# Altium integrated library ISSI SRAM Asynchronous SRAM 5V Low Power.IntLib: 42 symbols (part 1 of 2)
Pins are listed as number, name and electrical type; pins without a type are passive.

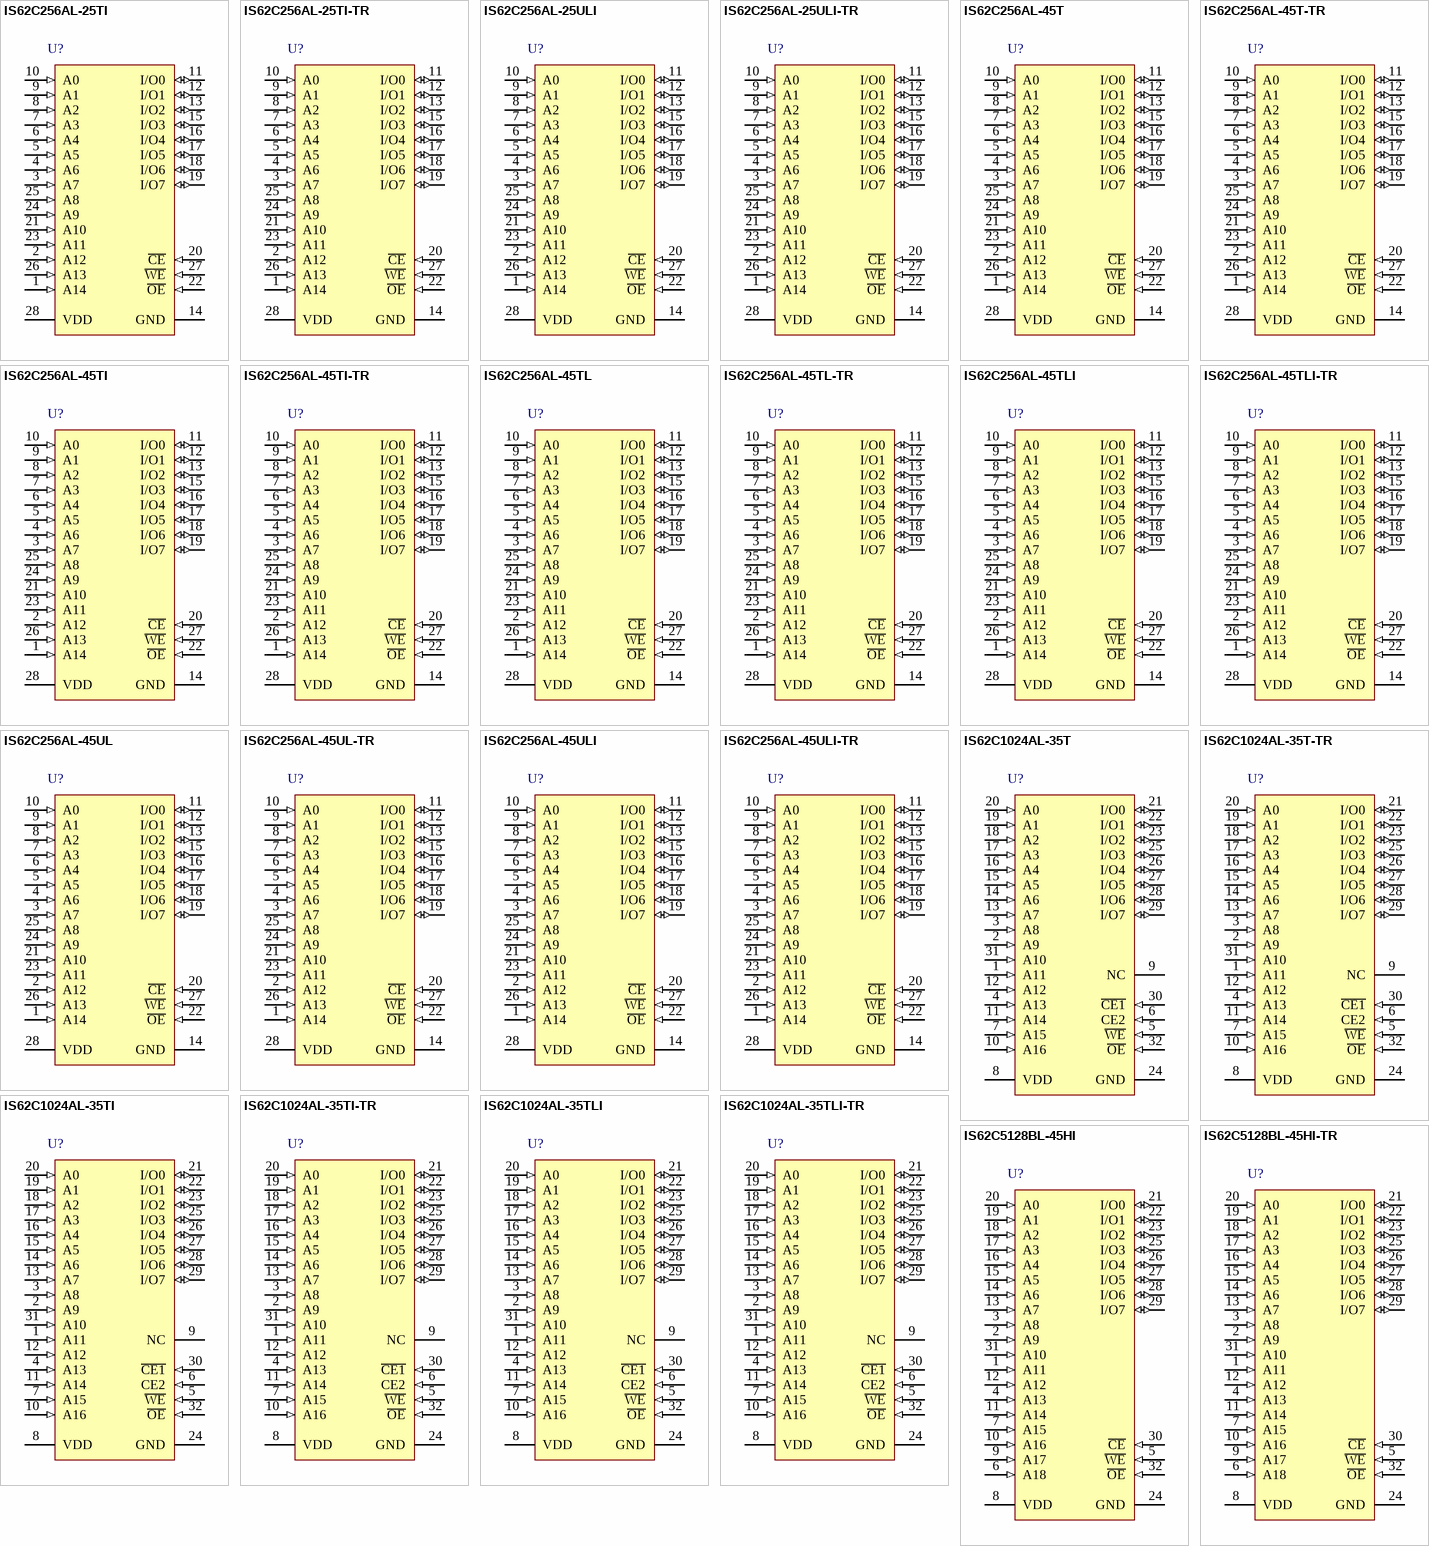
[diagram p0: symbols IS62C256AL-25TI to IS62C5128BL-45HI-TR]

## IS62C256AL-25TI
designator U?
256 K Low Power CMOS SRAM, 32 K x 8, -40 to 85 degC, 28-Pin SOP (TSOP-1-28); Manufacturer: Integrated Silicon Solution Inc (ISSI); PartNumber: IS62C256AL-25TI; Density: 256K; Organization: 32K x 8; Packing: Tray / Tube; Speed (ns): 25
footprint ISSI-TSOP-1-28-8000X13400DE_N (SOP, 28-Leads, Body 11.9x8.1mm, Pitch 0.55mm, IPC Medium Density)
pins: 1 A14 (in) "Address Input", 2 A12 (in) "Address Input", 3 A7 (in) "Address Input", 4 A6 (in) "Address Input", 5 A5 (in) "Address Input", 6 A4 (in) "Address Input", 7 A3 (in) "Address Input", 8 A2 (in) "Address Input", 9 A1 (in) "Address Input", 10 A0 (in) "Address Input", 11 I/O0 (io) "Input/Output", 12 I/O1 (io) "Input/Output", 13 I/O2 (io) "Input/Output", 14 GND (power) "Ground", 15 I/O3 (io) "Input/Output", 16 I/O4 (io) "Input/Output", 17 I/O5 (io) "Input/Output", 18 I/O6 (io) "Input/Output", 19 I/O7 (io) "Input/Output", 20 ~{CE} (in) "Chip Select Input", 21 A10 (in) "Address Input", 22 ~{OE} (in) "Output Enable Input", 23 A11 (in) "Address Input", 24 A9 (in) "Address Input", 25 A8 (in) "Address Input", 26 A13 (in) "Address Input", 27 ~{WE} (in) "Write Enable Input", 28 VDD (power) "Power"

## IS62C256AL-25TI-TR
designator U?
256 K Low Power CMOS SRAM, 32 K x 8, -40 to 85 degC, 28-Pin SOP (TSOP-1-28); Manufacturer: Integrated Silicon Solution Inc (ISSI); PartNumber: IS62C256AL-25TI-TR; Density: 256K; Organization: 32K x 8; Packing: Tape & Reel; Speed (ns): 25
footprint ISSI-TSOP-1-28-8000X13400DE_N (SOP, 28-Leads, Body 11.9x8.1mm, Pitch 0.55mm, IPC Medium Density)
pins: 1 A14 (in) "Address Input", 2 A12 (in) "Address Input", 3 A7 (in) "Address Input", 4 A6 (in) "Address Input", 5 A5 (in) "Address Input", 6 A4 (in) "Address Input", 7 A3 (in) "Address Input", 8 A2 (in) "Address Input", 9 A1 (in) "Address Input", 10 A0 (in) "Address Input", 11 I/O0 (io) "Input/Output", 12 I/O1 (io) "Input/Output", 13 I/O2 (io) "Input/Output", 14 GND (power) "Ground", 15 I/O3 (io) "Input/Output", 16 I/O4 (io) "Input/Output", 17 I/O5 (io) "Input/Output", 18 I/O6 (io) "Input/Output", 19 I/O7 (io) "Input/Output", 20 ~{CE} (in) "Chip Select Input", 21 A10 (in) "Address Input", 22 ~{OE} (in) "Output Enable Input", 23 A11 (in) "Address Input", 24 A9 (in) "Address Input", 25 A8 (in) "Address Input", 26 A13 (in) "Address Input", 27 ~{WE} (in) "Write Enable Input", 28 VDD (power) "Power"

## IS62C256AL-25ULI
designator U?
256 K Low Power CMOS SRAM, 32 K x 8, -40 to 85 degC, 28-Pin SOP (SOP-28), Pb-Free; Manufacturer: Integrated Silicon Solution Inc (ISSI); PartNumber: IS62C256AL-25ULI; Density: 256K; Organization: 32K x 8; Packing: Tray / Tube; Speed (ns): 25
footprint ISSI-SOP-28_N (SOP, 28-Leads, Body 18.66x8.9mm, Pitch 1.27mm, IPC Medium Density)
pins: 1 A14 (in) "Address Input", 2 A12 (in) "Address Input", 3 A7 (in) "Address Input", 4 A6 (in) "Address Input", 5 A5 (in) "Address Input", 6 A4 (in) "Address Input", 7 A3 (in) "Address Input", 8 A2 (in) "Address Input", 9 A1 (in) "Address Input", 10 A0 (in) "Address Input", 11 I/O0 (io) "Input/Output", 12 I/O1 (io) "Input/Output", 13 I/O2 (io) "Input/Output", 14 GND (power) "Ground", 15 I/O3 (io) "Input/Output", 16 I/O4 (io) "Input/Output", 17 I/O5 (io) "Input/Output", 18 I/O6 (io) "Input/Output", 19 I/O7 (io) "Input/Output", 20 ~{CE} (in) "Chip Select Input", 21 A10 (in) "Address Input", 22 ~{OE} (in) "Output Enable Input", 23 A11 (in) "Address Input", 24 A9 (in) "Address Input", 25 A8 (in) "Address Input", 26 A13 (in) "Address Input", 27 ~{WE} (in) "Write Enable Input", 28 VDD (power) "Power"

## IS62C256AL-25ULI-TR
designator U?
256 K Low Power CMOS SRAM, 32 K x 8, -40 to 85 degC, 28-Pin SOP (SOP-28), Pb-Free; Manufacturer: Integrated Silicon Solution Inc (ISSI); PartNumber: IS62C256AL-25ULI-TR; Density: 256K; Organization: 32K x 8; Packing: Tape & Reel; Speed (ns): 25
footprint ISSI-SOP-28_N (SOP, 28-Leads, Body 18.66x8.9mm, Pitch 1.27mm, IPC Medium Density)
pins: 1 A14 (in) "Address Input", 2 A12 (in) "Address Input", 3 A7 (in) "Address Input", 4 A6 (in) "Address Input", 5 A5 (in) "Address Input", 6 A4 (in) "Address Input", 7 A3 (in) "Address Input", 8 A2 (in) "Address Input", 9 A1 (in) "Address Input", 10 A0 (in) "Address Input", 11 I/O0 (io) "Input/Output", 12 I/O1 (io) "Input/Output", 13 I/O2 (io) "Input/Output", 14 GND (power) "Ground", 15 I/O3 (io) "Input/Output", 16 I/O4 (io) "Input/Output", 17 I/O5 (io) "Input/Output", 18 I/O6 (io) "Input/Output", 19 I/O7 (io) "Input/Output", 20 ~{CE} (in) "Chip Select Input", 21 A10 (in) "Address Input", 22 ~{OE} (in) "Output Enable Input", 23 A11 (in) "Address Input", 24 A9 (in) "Address Input", 25 A8 (in) "Address Input", 26 A13 (in) "Address Input", 27 ~{WE} (in) "Write Enable Input", 28 VDD (power) "Power"

## IS62C256AL-45T
designator U?
256 K Low Power CMOS SRAM, 32 K x 8, 0 to 70 degC, 28-Pin SOP (TSOP-1-28); Manufacturer: Integrated Silicon Solution Inc (ISSI); PartNumber: IS62C256AL-45T; Density: 256K; Organization: 32K x 8; Packing: Tray / Tube; Speed (ns): 45
footprint ISSI-TSOP-1-28-8000X13400DE_N (SOP, 28-Leads, Body 11.9x8.1mm, Pitch 0.55mm, IPC Medium Density)
pins: 1 A14 (in) "Address Input", 2 A12 (in) "Address Input", 3 A7 (in) "Address Input", 4 A6 (in) "Address Input", 5 A5 (in) "Address Input", 6 A4 (in) "Address Input", 7 A3 (in) "Address Input", 8 A2 (in) "Address Input", 9 A1 (in) "Address Input", 10 A0 (in) "Address Input", 11 I/O0 (io) "Input/Output", 12 I/O1 (io) "Input/Output", 13 I/O2 (io) "Input/Output", 14 GND (power) "Ground", 15 I/O3 (io) "Input/Output", 16 I/O4 (io) "Input/Output", 17 I/O5 (io) "Input/Output", 18 I/O6 (io) "Input/Output", 19 I/O7 (io) "Input/Output", 20 ~{CE} (in) "Chip Select Input", 21 A10 (in) "Address Input", 22 ~{OE} (in) "Output Enable Input", 23 A11 (in) "Address Input", 24 A9 (in) "Address Input", 25 A8 (in) "Address Input", 26 A13 (in) "Address Input", 27 ~{WE} (in) "Write Enable Input", 28 VDD (power) "Power"

## IS62C256AL-45T-TR
designator U?
256 K Low Power CMOS SRAM, 32 K x 8, 0 to 70 degC, 28-Pin SOP (TSOP-1-28); Manufacturer: Integrated Silicon Solution Inc (ISSI); PartNumber: IS62C256AL-45T-TR; Density: 256K; Organization: 32K x 8; Packing: Tape & Reel; Speed (ns): 45
footprint ISSI-TSOP-1-28-8000X13400DE_N (SOP, 28-Leads, Body 11.9x8.1mm, Pitch 0.55mm, IPC Medium Density)
pins: 1 A14 (in) "Address Input", 2 A12 (in) "Address Input", 3 A7 (in) "Address Input", 4 A6 (in) "Address Input", 5 A5 (in) "Address Input", 6 A4 (in) "Address Input", 7 A3 (in) "Address Input", 8 A2 (in) "Address Input", 9 A1 (in) "Address Input", 10 A0 (in) "Address Input", 11 I/O0 (io) "Input/Output", 12 I/O1 (io) "Input/Output", 13 I/O2 (io) "Input/Output", 14 GND (power) "Ground", 15 I/O3 (io) "Input/Output", 16 I/O4 (io) "Input/Output", 17 I/O5 (io) "Input/Output", 18 I/O6 (io) "Input/Output", 19 I/O7 (io) "Input/Output", 20 ~{CE} (in) "Chip Select Input", 21 A10 (in) "Address Input", 22 ~{OE} (in) "Output Enable Input", 23 A11 (in) "Address Input", 24 A9 (in) "Address Input", 25 A8 (in) "Address Input", 26 A13 (in) "Address Input", 27 ~{WE} (in) "Write Enable Input", 28 VDD (power) "Power"

## IS62C256AL-45TI
designator U?
256 K Low Power CMOS SRAM, 32 K x 8, -40 to 85 degC, 28-Pin SOP (TSOP-1-28); Manufacturer: Integrated Silicon Solution Inc (ISSI); PartNumber: IS62C256AL-45TI; Density: 256K; Organization: 32K x 8; Packing: Tray / Tube; Speed (ns): 45
footprint ISSI-TSOP-1-28-8000X13400DE_N (SOP, 28-Leads, Body 11.9x8.1mm, Pitch 0.55mm, IPC Medium Density)
pins: 1 A14 (in) "Address Input", 2 A12 (in) "Address Input", 3 A7 (in) "Address Input", 4 A6 (in) "Address Input", 5 A5 (in) "Address Input", 6 A4 (in) "Address Input", 7 A3 (in) "Address Input", 8 A2 (in) "Address Input", 9 A1 (in) "Address Input", 10 A0 (in) "Address Input", 11 I/O0 (io) "Input/Output", 12 I/O1 (io) "Input/Output", 13 I/O2 (io) "Input/Output", 14 GND (power) "Ground", 15 I/O3 (io) "Input/Output", 16 I/O4 (io) "Input/Output", 17 I/O5 (io) "Input/Output", 18 I/O6 (io) "Input/Output", 19 I/O7 (io) "Input/Output", 20 ~{CE} (in) "Chip Select Input", 21 A10 (in) "Address Input", 22 ~{OE} (in) "Output Enable Input", 23 A11 (in) "Address Input", 24 A9 (in) "Address Input", 25 A8 (in) "Address Input", 26 A13 (in) "Address Input", 27 ~{WE} (in) "Write Enable Input", 28 VDD (power) "Power"

## IS62C256AL-45TI-TR
designator U?
256 K Low Power CMOS SRAM, 32 K x 8, -40 to 85 degC, 28-Pin SOP (TSOP-1-28); Manufacturer: Integrated Silicon Solution Inc (ISSI); PartNumber: IS62C256AL-45TI-TR; Density: 256K; Organization: 32K x 8; Packing: Tape & Reel; Speed (ns): 45
footprint ISSI-TSOP-1-28-8000X13400DE_N (SOP, 28-Leads, Body 11.9x8.1mm, Pitch 0.55mm, IPC Medium Density)
pins: 1 A14 (in) "Address Input", 2 A12 (in) "Address Input", 3 A7 (in) "Address Input", 4 A6 (in) "Address Input", 5 A5 (in) "Address Input", 6 A4 (in) "Address Input", 7 A3 (in) "Address Input", 8 A2 (in) "Address Input", 9 A1 (in) "Address Input", 10 A0 (in) "Address Input", 11 I/O0 (io) "Input/Output", 12 I/O1 (io) "Input/Output", 13 I/O2 (io) "Input/Output", 14 GND (power) "Ground", 15 I/O3 (io) "Input/Output", 16 I/O4 (io) "Input/Output", 17 I/O5 (io) "Input/Output", 18 I/O6 (io) "Input/Output", 19 I/O7 (io) "Input/Output", 20 ~{CE} (in) "Chip Select Input", 21 A10 (in) "Address Input", 22 ~{OE} (in) "Output Enable Input", 23 A11 (in) "Address Input", 24 A9 (in) "Address Input", 25 A8 (in) "Address Input", 26 A13 (in) "Address Input", 27 ~{WE} (in) "Write Enable Input", 28 VDD (power) "Power"

## IS62C256AL-45TL
designator U?
256 K Low Power CMOS SRAM, 32 K x 8, 0 to 70 degC, 28-Pin SOP (TSOP-1-28), Pb-Free; Manufacturer: Integrated Silicon Solution Inc (ISSI); PartNumber: IS62C256AL-45TL; Density: 256K; Organization: 32K x 8; Packing: Tray / Tube; Speed (ns): 45
footprint ISSI-TSOP-1-28-8000X13400DE_N (SOP, 28-Leads, Body 11.9x8.1mm, Pitch 0.55mm, IPC Medium Density)
pins: 1 A14 (in) "Address Input", 2 A12 (in) "Address Input", 3 A7 (in) "Address Input", 4 A6 (in) "Address Input", 5 A5 (in) "Address Input", 6 A4 (in) "Address Input", 7 A3 (in) "Address Input", 8 A2 (in) "Address Input", 9 A1 (in) "Address Input", 10 A0 (in) "Address Input", 11 I/O0 (io) "Input/Output", 12 I/O1 (io) "Input/Output", 13 I/O2 (io) "Input/Output", 14 GND (power) "Ground", 15 I/O3 (io) "Input/Output", 16 I/O4 (io) "Input/Output", 17 I/O5 (io) "Input/Output", 18 I/O6 (io) "Input/Output", 19 I/O7 (io) "Input/Output", 20 ~{CE} (in) "Chip Select Input", 21 A10 (in) "Address Input", 22 ~{OE} (in) "Output Enable Input", 23 A11 (in) "Address Input", 24 A9 (in) "Address Input", 25 A8 (in) "Address Input", 26 A13 (in) "Address Input", 27 ~{WE} (in) "Write Enable Input", 28 VDD (power) "Power"

## IS62C256AL-45TL-TR
designator U?
256 K Low Power CMOS SRAM, 32 K x 8, 0 to 70 degC, 28-Pin SOP (TSOP-1-28), Pb-Free; Manufacturer: Integrated Silicon Solution Inc (ISSI); PartNumber: IS62C256AL-45TL-TR; Density: 256K; Organization: 32K x 8; Packing: Tape & Reel; Speed (ns): 45
footprint ISSI-TSOP-1-28-8000X13400DE_N (SOP, 28-Leads, Body 11.9x8.1mm, Pitch 0.55mm, IPC Medium Density)
pins: 1 A14 (in) "Address Input", 2 A12 (in) "Address Input", 3 A7 (in) "Address Input", 4 A6 (in) "Address Input", 5 A5 (in) "Address Input", 6 A4 (in) "Address Input", 7 A3 (in) "Address Input", 8 A2 (in) "Address Input", 9 A1 (in) "Address Input", 10 A0 (in) "Address Input", 11 I/O0 (io) "Input/Output", 12 I/O1 (io) "Input/Output", 13 I/O2 (io) "Input/Output", 14 GND (power) "Ground", 15 I/O3 (io) "Input/Output", 16 I/O4 (io) "Input/Output", 17 I/O5 (io) "Input/Output", 18 I/O6 (io) "Input/Output", 19 I/O7 (io) "Input/Output", 20 ~{CE} (in) "Chip Select Input", 21 A10 (in) "Address Input", 22 ~{OE} (in) "Output Enable Input", 23 A11 (in) "Address Input", 24 A9 (in) "Address Input", 25 A8 (in) "Address Input", 26 A13 (in) "Address Input", 27 ~{WE} (in) "Write Enable Input", 28 VDD (power) "Power"

## IS62C256AL-45TLI
designator U?
256 K Low Power CMOS SRAM, 32 K x 8, -40 to 85 degC, 28-Pin SOP (TSOP-1-28), Pb-Free; Manufacturer: Integrated Silicon Solution Inc (ISSI); PartNumber: IS62C256AL-45TLI; Density: 256K; Organization: 32K x 8; Packing: Tray / Tube; Speed (ns): 45
footprint ISSI-TSOP-1-28-8000X13400DE_N (SOP, 28-Leads, Body 11.9x8.1mm, Pitch 0.55mm, IPC Medium Density)
pins: 1 A14 (in) "Address Input", 2 A12 (in) "Address Input", 3 A7 (in) "Address Input", 4 A6 (in) "Address Input", 5 A5 (in) "Address Input", 6 A4 (in) "Address Input", 7 A3 (in) "Address Input", 8 A2 (in) "Address Input", 9 A1 (in) "Address Input", 10 A0 (in) "Address Input", 11 I/O0 (io) "Input/Output", 12 I/O1 (io) "Input/Output", 13 I/O2 (io) "Input/Output", 14 GND (power) "Ground", 15 I/O3 (io) "Input/Output", 16 I/O4 (io) "Input/Output", 17 I/O5 (io) "Input/Output", 18 I/O6 (io) "Input/Output", 19 I/O7 (io) "Input/Output", 20 ~{CE} (in) "Chip Select Input", 21 A10 (in) "Address Input", 22 ~{OE} (in) "Output Enable Input", 23 A11 (in) "Address Input", 24 A9 (in) "Address Input", 25 A8 (in) "Address Input", 26 A13 (in) "Address Input", 27 ~{WE} (in) "Write Enable Input", 28 VDD (power) "Power"

## IS62C256AL-45TLI-TR
designator U?
256 K Low Power CMOS SRAM, 32 K x 8, -40 to 85 degC, 28-Pin SOP (TSOP-1-28), Pb-Free; Manufacturer: Integrated Silicon Solution Inc (ISSI); PartNumber: IS62C256AL-45TLI-TR; Density: 256K; Organization: 32K x 8; Packing: Tape & Reel; Speed (ns): 45
footprint ISSI-TSOP-1-28-8000X13400DE_N (SOP, 28-Leads, Body 11.9x8.1mm, Pitch 0.55mm, IPC Medium Density)
pins: 1 A14 (in) "Address Input", 2 A12 (in) "Address Input", 3 A7 (in) "Address Input", 4 A6 (in) "Address Input", 5 A5 (in) "Address Input", 6 A4 (in) "Address Input", 7 A3 (in) "Address Input", 8 A2 (in) "Address Input", 9 A1 (in) "Address Input", 10 A0 (in) "Address Input", 11 I/O0 (io) "Input/Output", 12 I/O1 (io) "Input/Output", 13 I/O2 (io) "Input/Output", 14 GND (power) "Ground", 15 I/O3 (io) "Input/Output", 16 I/O4 (io) "Input/Output", 17 I/O5 (io) "Input/Output", 18 I/O6 (io) "Input/Output", 19 I/O7 (io) "Input/Output", 20 ~{CE} (in) "Chip Select Input", 21 A10 (in) "Address Input", 22 ~{OE} (in) "Output Enable Input", 23 A11 (in) "Address Input", 24 A9 (in) "Address Input", 25 A8 (in) "Address Input", 26 A13 (in) "Address Input", 27 ~{WE} (in) "Write Enable Input", 28 VDD (power) "Power"

## IS62C256AL-45UL
designator U?
256 K Low Power CMOS SRAM, 32 K x 8, 0 to 70 degC, 28-Pin SOP (SOP-28), Pb-Free; Manufacturer: Integrated Silicon Solution Inc (ISSI); PartNumber: IS62C256AL-45UL; Density: 256K; Organization: 32K x 8; Packing: Tray / Tube; Speed (ns): 45
footprint ISSI-SOP-28_N (SOP, 28-Leads, Body 18.66x8.9mm, Pitch 1.27mm, IPC Medium Density)
pins: 1 A14 (in) "Address Input", 2 A12 (in) "Address Input", 3 A7 (in) "Address Input", 4 A6 (in) "Address Input", 5 A5 (in) "Address Input", 6 A4 (in) "Address Input", 7 A3 (in) "Address Input", 8 A2 (in) "Address Input", 9 A1 (in) "Address Input", 10 A0 (in) "Address Input", 11 I/O0 (io) "Input/Output", 12 I/O1 (io) "Input/Output", 13 I/O2 (io) "Input/Output", 14 GND (power) "Ground", 15 I/O3 (io) "Input/Output", 16 I/O4 (io) "Input/Output", 17 I/O5 (io) "Input/Output", 18 I/O6 (io) "Input/Output", 19 I/O7 (io) "Input/Output", 20 ~{CE} (in) "Chip Select Input", 21 A10 (in) "Address Input", 22 ~{OE} (in) "Output Enable Input", 23 A11 (in) "Address Input", 24 A9 (in) "Address Input", 25 A8 (in) "Address Input", 26 A13 (in) "Address Input", 27 ~{WE} (in) "Write Enable Input", 28 VDD (power) "Power"

## IS62C256AL-45UL-TR
designator U?
256 K Low Power CMOS SRAM, 32 K x 8, 0 to 70 degC, 28-Pin SOP (SOP-28), Pb-Free; Manufacturer: Integrated Silicon Solution Inc (ISSI); PartNumber: IS62C256AL-45UL-TR; Density: 256K; Organization: 32K x 8; Packing: Tape & Reel; Speed (ns): 45
footprint ISSI-SOP-28_N (SOP, 28-Leads, Body 18.66x8.9mm, Pitch 1.27mm, IPC Medium Density)
pins: 1 A14 (in) "Address Input", 2 A12 (in) "Address Input", 3 A7 (in) "Address Input", 4 A6 (in) "Address Input", 5 A5 (in) "Address Input", 6 A4 (in) "Address Input", 7 A3 (in) "Address Input", 8 A2 (in) "Address Input", 9 A1 (in) "Address Input", 10 A0 (in) "Address Input", 11 I/O0 (io) "Input/Output", 12 I/O1 (io) "Input/Output", 13 I/O2 (io) "Input/Output", 14 GND (power) "Ground", 15 I/O3 (io) "Input/Output", 16 I/O4 (io) "Input/Output", 17 I/O5 (io) "Input/Output", 18 I/O6 (io) "Input/Output", 19 I/O7 (io) "Input/Output", 20 ~{CE} (in) "Chip Select Input", 21 A10 (in) "Address Input", 22 ~{OE} (in) "Output Enable Input", 23 A11 (in) "Address Input", 24 A9 (in) "Address Input", 25 A8 (in) "Address Input", 26 A13 (in) "Address Input", 27 ~{WE} (in) "Write Enable Input", 28 VDD (power) "Power"

## IS62C256AL-45ULI
designator U?
256 K Low Power CMOS SRAM, 32 K x 8, -40 to 85 degC, 28-Pin SOP (SOP-28), Pb-Free; Manufacturer: Integrated Silicon Solution Inc (ISSI); PartNumber: IS62C256AL-45ULI; Density: 256K; Organization: 32K x 8; Packing: Tray / Tube; Speed (ns): 45
footprint ISSI-SOP-28_N (SOP, 28-Leads, Body 18.66x8.9mm, Pitch 1.27mm, IPC Medium Density)
pins: 1 A14 (in) "Address Input", 2 A12 (in) "Address Input", 3 A7 (in) "Address Input", 4 A6 (in) "Address Input", 5 A5 (in) "Address Input", 6 A4 (in) "Address Input", 7 A3 (in) "Address Input", 8 A2 (in) "Address Input", 9 A1 (in) "Address Input", 10 A0 (in) "Address Input", 11 I/O0 (io) "Input/Output", 12 I/O1 (io) "Input/Output", 13 I/O2 (io) "Input/Output", 14 GND (power) "Ground", 15 I/O3 (io) "Input/Output", 16 I/O4 (io) "Input/Output", 17 I/O5 (io) "Input/Output", 18 I/O6 (io) "Input/Output", 19 I/O7 (io) "Input/Output", 20 ~{CE} (in) "Chip Select Input", 21 A10 (in) "Address Input", 22 ~{OE} (in) "Output Enable Input", 23 A11 (in) "Address Input", 24 A9 (in) "Address Input", 25 A8 (in) "Address Input", 26 A13 (in) "Address Input", 27 ~{WE} (in) "Write Enable Input", 28 VDD (power) "Power"

## IS62C256AL-45ULI-TR
designator U?
256 K Low Power CMOS SRAM, 32 K x 8, -40 to 85 degC, 28-Pin SOP (SOP-28), Pb-Free; Manufacturer: Integrated Silicon Solution Inc (ISSI); PartNumber: IS62C256AL-45ULI-TR; Density: 256K; Organization: 32K x 8; Packing: Tape & Reel; Speed (ns): 45
footprint ISSI-SOP-28_N (SOP, 28-Leads, Body 18.66x8.9mm, Pitch 1.27mm, IPC Medium Density)
pins: 1 A14 (in) "Address Input", 2 A12 (in) "Address Input", 3 A7 (in) "Address Input", 4 A6 (in) "Address Input", 5 A5 (in) "Address Input", 6 A4 (in) "Address Input", 7 A3 (in) "Address Input", 8 A2 (in) "Address Input", 9 A1 (in) "Address Input", 10 A0 (in) "Address Input", 11 I/O0 (io) "Input/Output", 12 I/O1 (io) "Input/Output", 13 I/O2 (io) "Input/Output", 14 GND (power) "Ground", 15 I/O3 (io) "Input/Output", 16 I/O4 (io) "Input/Output", 17 I/O5 (io) "Input/Output", 18 I/O6 (io) "Input/Output", 19 I/O7 (io) "Input/Output", 20 ~{CE} (in) "Chip Select Input", 21 A10 (in) "Address Input", 22 ~{OE} (in) "Output Enable Input", 23 A11 (in) "Address Input", 24 A9 (in) "Address Input", 25 A8 (in) "Address Input", 26 A13 (in) "Address Input", 27 ~{WE} (in) "Write Enable Input", 28 VDD (power) "Power"

## IS62C1024AL-35T
designator U?
1 M Low Power CMOS SRAM, 128 K x 8, 0 to 70 degC, 32-Pin SOP (TSOP-1-32); Manufacturer: Integrated Silicon Solution Inc (ISSI); PartNumber: IS62C1024AL-35T; Density: 1M; Organization: 128K x 8; Packing: Tray / Tube; Speed (ns): 35
footprint ISSI-TSOP-1-32-8000x20000DE_N (SOP, 32-Leads, Body 18.5x8.2mm, Pitch 0.5mm, IPC Medium Density)
pins: 1 A11 (in) "Address Input", 2 A9 (in) "Address Input", 3 A8 (in) "Address Input", 4 A13 (in) "Address Input", 5 ~{WE} (in) "Write Enable Input", 6 CE2 (in) "Chip Enable 2 Input", 7 A15 (in) "Address Input", 8 VDD (power) "Power", 9 NC, 10 A16 (in) "Address Input", 11 A14 (in) "Address Input", 12 A12 (in) "Address Input", 13 A7 (in) "Address Input", 14 A6 (in) "Address Input", 15 A5 (in) "Address Input", 16 A4 (in) "Address Input", 17 A3 (in) "Address Input", 18 A2 (in) "Address Input", 19 A1 (in) "Address Input", 20 A0 (in) "Address Input", 21 I/O0 (io) "Input/Output", 22 I/O1 (io) "Input/Output", 23 I/O2 (io) "Input/Output", 24 GND (power) "Ground", 25 I/O3 (io) "Input/Output", 26 I/O4 (io) "Input/Output", 27 I/O5 (io) "Input/Output", 28 I/O6 (io) "Input/Output", 29 I/O7 (io) "Input/Output", 30 ~{CE1} (in) "Chip Enable 1 Input", 31 A10 (in) "Address Input", 32 ~{OE} (in) "Output Enable Input"

## IS62C1024AL-35T-TR
designator U?
1 M Low Power CMOS SRAM, 128 K x 8, 0 to 70 degC, 32-Pin SOP (TSOP-1-32); Manufacturer: Integrated Silicon Solution Inc (ISSI); PartNumber: IS62C1024AL-35T-TR; Density: 1M; Organization: 128K x 8; Packing: Tape & Reel; Speed (ns): 35
footprint ISSI-TSOP-1-32-8000x20000DE_N (SOP, 32-Leads, Body 18.5x8.2mm, Pitch 0.5mm, IPC Medium Density)
pins: 1 A11 (in) "Address Input", 2 A9 (in) "Address Input", 3 A8 (in) "Address Input", 4 A13 (in) "Address Input", 5 ~{WE} (in) "Write Enable Input", 6 CE2 (in) "Chip Enable 2 Input", 7 A15 (in) "Address Input", 8 VDD (power) "Power", 9 NC, 10 A16 (in) "Address Input", 11 A14 (in) "Address Input", 12 A12 (in) "Address Input", 13 A7 (in) "Address Input", 14 A6 (in) "Address Input", 15 A5 (in) "Address Input", 16 A4 (in) "Address Input", 17 A3 (in) "Address Input", 18 A2 (in) "Address Input", 19 A1 (in) "Address Input", 20 A0 (in) "Address Input", 21 I/O0 (io) "Input/Output", 22 I/O1 (io) "Input/Output", 23 I/O2 (io) "Input/Output", 24 GND (power) "Ground", 25 I/O3 (io) "Input/Output", 26 I/O4 (io) "Input/Output", 27 I/O5 (io) "Input/Output", 28 I/O6 (io) "Input/Output", 29 I/O7 (io) "Input/Output", 30 ~{CE1} (in) "Chip Enable 1 Input", 31 A10 (in) "Address Input", 32 ~{OE} (in) "Output Enable Input"

## IS62C1024AL-35TI
designator U?
1 M Low Power CMOS SRAM, 128 K x 8, -40 to 85 degC, 32-Pin SOP (TSOP-1-32); Manufacturer: Integrated Silicon Solution Inc (ISSI); PartNumber: IS62C1024AL-35TI; Density: 1M; Organization: 128K x 8; Packing: Tray / Tube; Speed (ns): 35
footprint ISSI-TSOP-1-32-8000x20000DE_N (SOP, 32-Leads, Body 18.5x8.2mm, Pitch 0.5mm, IPC Medium Density)
pins: 1 A11 (in) "Address Input", 2 A9 (in) "Address Input", 3 A8 (in) "Address Input", 4 A13 (in) "Address Input", 5 ~{WE} (in) "Write Enable Input", 6 CE2 (in) "Chip Enable 2 Input", 7 A15 (in) "Address Input", 8 VDD (power) "Power", 9 NC, 10 A16 (in) "Address Input", 11 A14 (in) "Address Input", 12 A12 (in) "Address Input", 13 A7 (in) "Address Input", 14 A6 (in) "Address Input", 15 A5 (in) "Address Input", 16 A4 (in) "Address Input", 17 A3 (in) "Address Input", 18 A2 (in) "Address Input", 19 A1 (in) "Address Input", 20 A0 (in) "Address Input", 21 I/O0 (io) "Input/Output", 22 I/O1 (io) "Input/Output", 23 I/O2 (io) "Input/Output", 24 GND (power) "Ground", 25 I/O3 (io) "Input/Output", 26 I/O4 (io) "Input/Output", 27 I/O5 (io) "Input/Output", 28 I/O6 (io) "Input/Output", 29 I/O7 (io) "Input/Output", 30 ~{CE1} (in) "Chip Enable 1 Input", 31 A10 (in) "Address Input", 32 ~{OE} (in) "Output Enable Input"

## IS62C1024AL-35TI-TR
designator U?
1 M Low Power CMOS SRAM, 128 K x 8, -40 to 85 degC, 32-Pin SOP (TSOP-1-32); Manufacturer: Integrated Silicon Solution Inc (ISSI); PartNumber: IS62C1024AL-35TI-TR; Density: 1M; Organization: 128K x 8; Packing: Tape & Reel; Speed (ns): 35
footprint ISSI-TSOP-1-32-8000x20000DE_N (SOP, 32-Leads, Body 18.5x8.2mm, Pitch 0.5mm, IPC Medium Density)
pins: 1 A11 (in) "Address Input", 2 A9 (in) "Address Input", 3 A8 (in) "Address Input", 4 A13 (in) "Address Input", 5 ~{WE} (in) "Write Enable Input", 6 CE2 (in) "Chip Enable 2 Input", 7 A15 (in) "Address Input", 8 VDD (power) "Power", 9 NC, 10 A16 (in) "Address Input", 11 A14 (in) "Address Input", 12 A12 (in) "Address Input", 13 A7 (in) "Address Input", 14 A6 (in) "Address Input", 15 A5 (in) "Address Input", 16 A4 (in) "Address Input", 17 A3 (in) "Address Input", 18 A2 (in) "Address Input", 19 A1 (in) "Address Input", 20 A0 (in) "Address Input", 21 I/O0 (io) "Input/Output", 22 I/O1 (io) "Input/Output", 23 I/O2 (io) "Input/Output", 24 GND (power) "Ground", 25 I/O3 (io) "Input/Output", 26 I/O4 (io) "Input/Output", 27 I/O5 (io) "Input/Output", 28 I/O6 (io) "Input/Output", 29 I/O7 (io) "Input/Output", 30 ~{CE1} (in) "Chip Enable 1 Input", 31 A10 (in) "Address Input", 32 ~{OE} (in) "Output Enable Input"

## IS62C1024AL-35TLI
designator U?
1 M Low Power CMOS SRAM, 128 K x 8, -40 to 85 degC, 32-Pin SOP (TSOP-1-32), Pb-Free; Manufacturer: Integrated Silicon Solution Inc (ISSI); PartNumber: IS62C1024AL-35TLI; Density: 1M; Organization: 128K x 8; Packing: Tray / Tube; Speed (ns): 35
footprint ISSI-TSOP-1-32-8000x20000DE_N (SOP, 32-Leads, Body 18.5x8.2mm, Pitch 0.5mm, IPC Medium Density)
pins: 1 A11 (in) "Address Input", 2 A9 (in) "Address Input", 3 A8 (in) "Address Input", 4 A13 (in) "Address Input", 5 ~{WE} (in) "Write Enable Input", 6 CE2 (in) "Chip Enable 2 Input", 7 A15 (in) "Address Input", 8 VDD (power) "Power", 9 NC, 10 A16 (in) "Address Input", 11 A14 (in) "Address Input", 12 A12 (in) "Address Input", 13 A7 (in) "Address Input", 14 A6 (in) "Address Input", 15 A5 (in) "Address Input", 16 A4 (in) "Address Input", 17 A3 (in) "Address Input", 18 A2 (in) "Address Input", 19 A1 (in) "Address Input", 20 A0 (in) "Address Input", 21 I/O0 (io) "Input/Output", 22 I/O1 (io) "Input/Output", 23 I/O2 (io) "Input/Output", 24 GND (power) "Ground", 25 I/O3 (io) "Input/Output", 26 I/O4 (io) "Input/Output", 27 I/O5 (io) "Input/Output", 28 I/O6 (io) "Input/Output", 29 I/O7 (io) "Input/Output", 30 ~{CE1} (in) "Chip Enable 1 Input", 31 A10 (in) "Address Input", 32 ~{OE} (in) "Output Enable Input"

## IS62C1024AL-35TLI-TR
designator U?
1 M Low Power CMOS SRAM, 128 K x 8, -40 to 85 degC, 32-Pin SOP (TSOP-1-32), Pb-Free; Manufacturer: Integrated Silicon Solution Inc (ISSI); PartNumber: IS62C1024AL-35TLI-TR; Density: 1M; Organization: 128K x 8; Packing: Tape & Reel; Speed (ns): 35
footprint ISSI-TSOP-1-32-8000x20000DE_N (SOP, 32-Leads, Body 18.5x8.2mm, Pitch 0.5mm, IPC Medium Density)
pins: 1 A11 (in) "Address Input", 2 A9 (in) "Address Input", 3 A8 (in) "Address Input", 4 A13 (in) "Address Input", 5 ~{WE} (in) "Write Enable Input", 6 CE2 (in) "Chip Enable 2 Input", 7 A15 (in) "Address Input", 8 VDD (power) "Power", 9 NC, 10 A16 (in) "Address Input", 11 A14 (in) "Address Input", 12 A12 (in) "Address Input", 13 A7 (in) "Address Input", 14 A6 (in) "Address Input", 15 A5 (in) "Address Input", 16 A4 (in) "Address Input", 17 A3 (in) "Address Input", 18 A2 (in) "Address Input", 19 A1 (in) "Address Input", 20 A0 (in) "Address Input", 21 I/O0 (io) "Input/Output", 22 I/O1 (io) "Input/Output", 23 I/O2 (io) "Input/Output", 24 GND (power) "Ground", 25 I/O3 (io) "Input/Output", 26 I/O4 (io) "Input/Output", 27 I/O5 (io) "Input/Output", 28 I/O6 (io) "Input/Output", 29 I/O7 (io) "Input/Output", 30 ~{CE1} (in) "Chip Enable 1 Input", 31 A10 (in) "Address Input", 32 ~{OE} (in) "Output Enable Input"

## IS62C5128BL-45HI
designator U?
4 M High Speed CMOS SRAM, 512 K x 8, -40 to 85 degC, 32-Pin SOP (TSOP-1-32); Manufacturer: Integrated Silicon Solution Inc (ISSI); PartNumber: IS62C5128BL-45HI; Density: 4M; Organization: 512K x 8; Packing: Tray / Tube; Speed (ns): 45
footprint ISSI-TSOP-1-32-8000x13400DE_N (SOP, 32-Leads, Body 11.9x8.1mm, Pitch 0.5mm, IPC Medium Density)
pins: 1 A11 (in) "Address Input", 2 A9 (in) "Address Input", 3 A8 (in) "Address Input", 4 A13 (in) "Address Input", 5 ~{WE} (in) "Write Enable Input", 6 A18 (in) "Address Input", 7 A15 (in) "Address Input", 8 VDD (power) "Power", 9 A17 (in) "Address Input", 10 A16 (in) "Address Input", 11 A14 (in) "Address Input", 12 A12 (in) "Address Input", 13 A7 (in) "Address Input", 14 A6 (in) "Address Input", 15 A5 (in) "Address Input", 16 A4 (in) "Address Input", 17 A3 (in) "Address Input", 18 A2 (in) "Address Input", 19 A1 (in) "Address Input", 20 A0 (in) "Address Input", 21 I/O0 (io) "Input/Output", 22 I/O1 (io) "Input/Output", 23 I/O2 (io) "Input/Output", 24 GND (power) "Ground", 25 I/O3 (io) "Input/Output", 26 I/O4 (io) "Input/Output", 27 I/O5 (io) "Input/Output", 28 I/O6 (io) "Input/Output", 29 I/O7 (io) "Input/Output", 30 ~{CE} (in) "Chip Enable 1 Input", 31 A10 (in) "Address Input", 32 ~{OE} (in) "Output Enable Input"

## IS62C5128BL-45HI-TR
designator U?
4 M High Speed CMOS SRAM, 512 K x 8, -40 to 85 degC, 32-Pin SOP (TSOP-1-32); Manufacturer: Integrated Silicon Solution Inc (ISSI); PartNumber: IS62C5128BL-45HI-TR; Density: 4M; Organization: 512K x 8; Packing: Tape & Reel; Speed (ns): 45
footprint ISSI-TSOP-1-32-8000x13400DE_N (SOP, 32-Leads, Body 11.9x8.1mm, Pitch 0.5mm, IPC Medium Density)
pins: 1 A11 (in) "Address Input", 2 A9 (in) "Address Input", 3 A8 (in) "Address Input", 4 A13 (in) "Address Input", 5 ~{WE} (in) "Write Enable Input", 6 A18 (in) "Address Input", 7 A15 (in) "Address Input", 8 VDD (power) "Power", 9 A17 (in) "Address Input", 10 A16 (in) "Address Input", 11 A14 (in) "Address Input", 12 A12 (in) "Address Input", 13 A7 (in) "Address Input", 14 A6 (in) "Address Input", 15 A5 (in) "Address Input", 16 A4 (in) "Address Input", 17 A3 (in) "Address Input", 18 A2 (in) "Address Input", 19 A1 (in) "Address Input", 20 A0 (in) "Address Input", 21 I/O0 (io) "Input/Output", 22 I/O1 (io) "Input/Output", 23 I/O2 (io) "Input/Output", 24 GND (power) "Ground", 25 I/O3 (io) "Input/Output", 26 I/O4 (io) "Input/Output", 27 I/O5 (io) "Input/Output", 28 I/O6 (io) "Input/Output", 29 I/O7 (io) "Input/Output", 30 ~{CE} (in) "Chip Enable 1 Input", 31 A10 (in) "Address Input", 32 ~{OE} (in) "Output Enable Input"

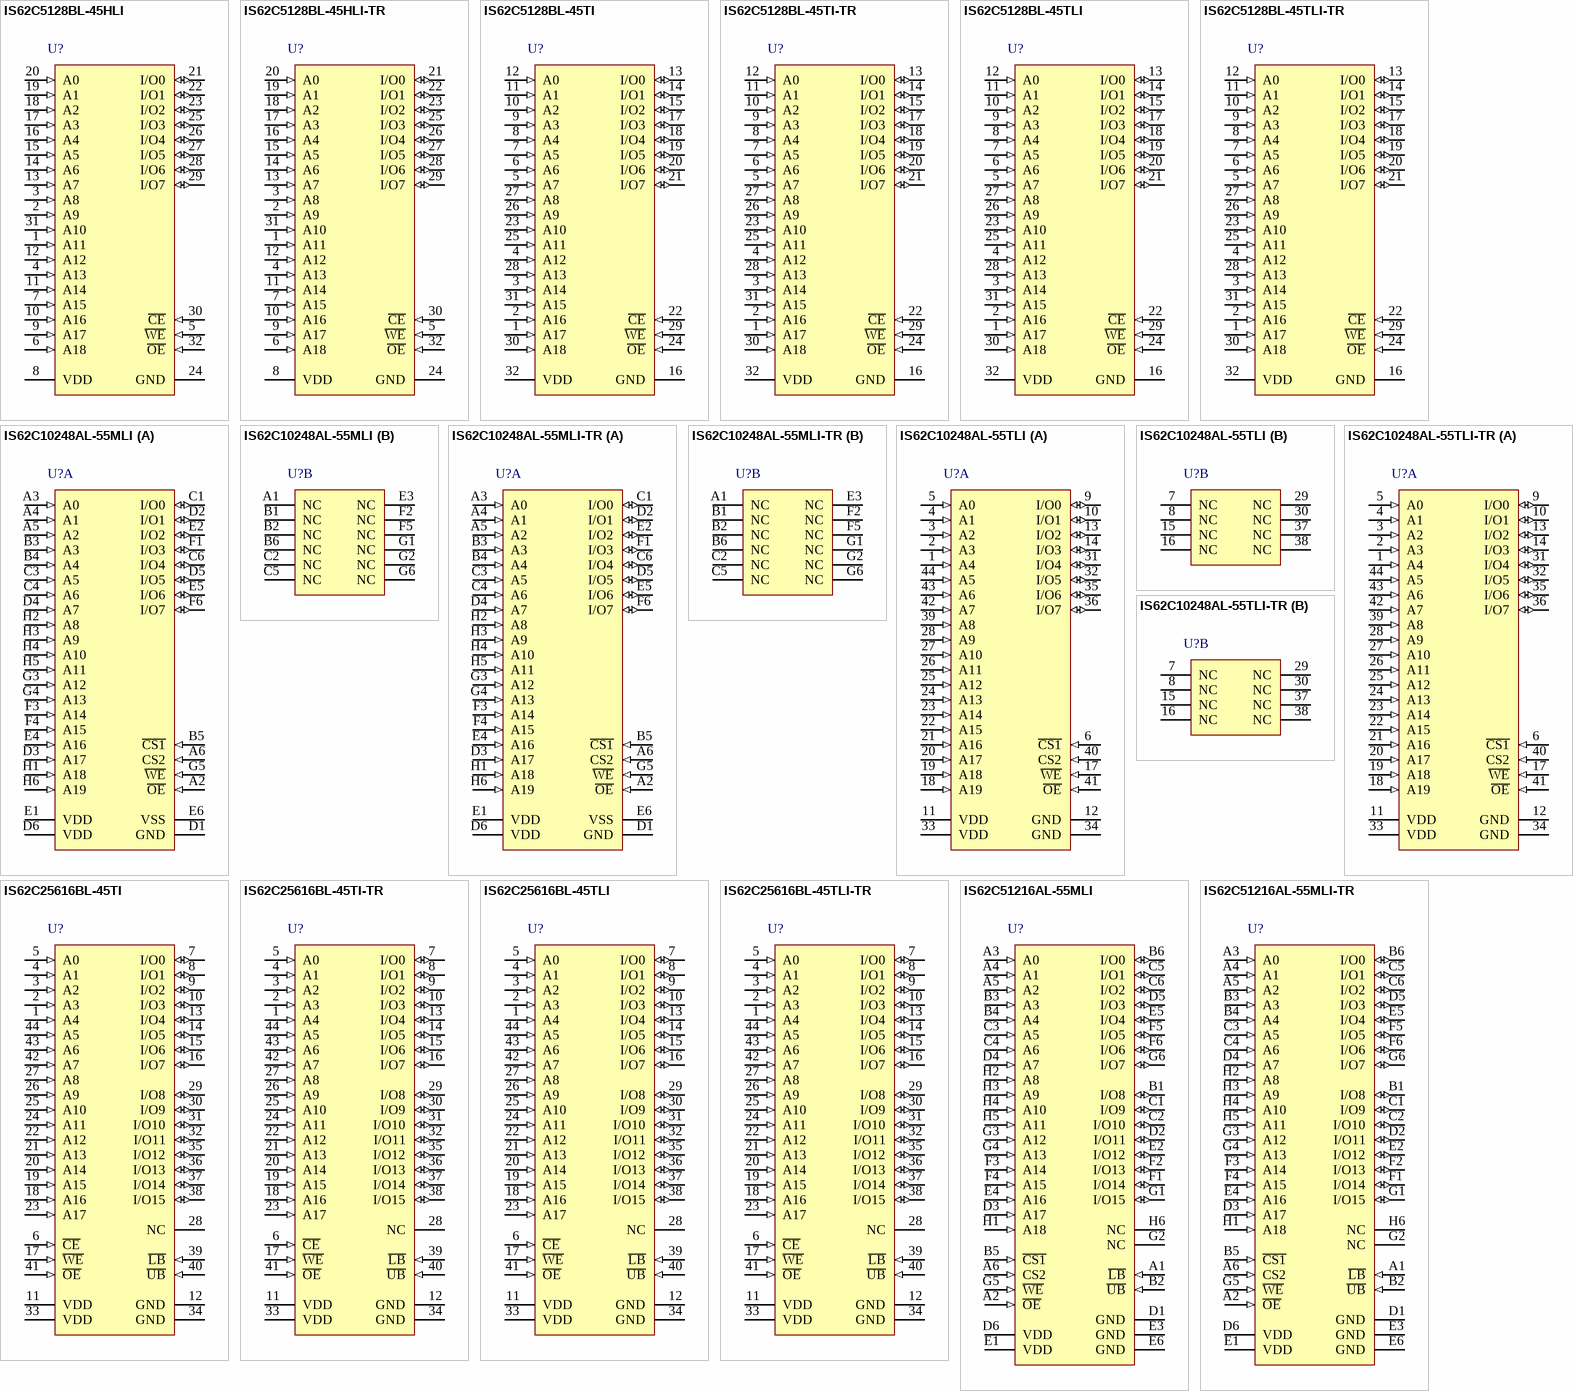
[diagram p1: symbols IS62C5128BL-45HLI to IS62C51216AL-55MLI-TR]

## IS62C5128BL-45HLI
designator U?
4 M High Speed CMOS SRAM, 512 K x 8, -40 to 85 degC, 32-Pin SOP (TSOP-1-32), Pb-Free; Manufacturer: Integrated Silicon Solution Inc (ISSI); PartNumber: IS62C5128BL-45HLI; Density: 4M; Organization: 512K x 8; Packing: Tray / Tube; Speed (ns): 45
footprint ISSI-TSOP-1-32-8000x13400DE_N (SOP, 32-Leads, Body 11.9x8.1mm, Pitch 0.5mm, IPC Medium Density)
pins: 1 A11 (in) "Address Input", 2 A9 (in) "Address Input", 3 A8 (in) "Address Input", 4 A13 (in) "Address Input", 5 ~{WE} (in) "Write Enable Input", 6 A18 (in) "Address Input", 7 A15 (in) "Address Input", 8 VDD (power) "Power", 9 A17 (in) "Address Input", 10 A16 (in) "Address Input", 11 A14 (in) "Address Input", 12 A12 (in) "Address Input", 13 A7 (in) "Address Input", 14 A6 (in) "Address Input", 15 A5 (in) "Address Input", 16 A4 (in) "Address Input", 17 A3 (in) "Address Input", 18 A2 (in) "Address Input", 19 A1 (in) "Address Input", 20 A0 (in) "Address Input", 21 I/O0 (io) "Input/Output", 22 I/O1 (io) "Input/Output", 23 I/O2 (io) "Input/Output", 24 GND (power) "Ground", 25 I/O3 (io) "Input/Output", 26 I/O4 (io) "Input/Output", 27 I/O5 (io) "Input/Output", 28 I/O6 (io) "Input/Output", 29 I/O7 (io) "Input/Output", 30 ~{CE} (in) "Chip Enable 1 Input", 31 A10 (in) "Address Input", 32 ~{OE} (in) "Output Enable Input"

## IS62C5128BL-45HLI-TR
designator U?
4 M High Speed CMOS SRAM, 512 K x 8, -40 to 85 degC, 32-Pin SOP (TSOP-1-32), Pb-Free; Manufacturer: Integrated Silicon Solution Inc (ISSI); PartNumber: IS62C5128BL-45HLI-TR; Density: 4M; Organization: 512K x 8; Packing: Tape & Reel; Speed (ns): 45
footprint ISSI-TSOP-1-32-8000x13400DE_N (SOP, 32-Leads, Body 11.9x8.1mm, Pitch 0.5mm, IPC Medium Density)
pins: 1 A11 (in) "Address Input", 2 A9 (in) "Address Input", 3 A8 (in) "Address Input", 4 A13 (in) "Address Input", 5 ~{WE} (in) "Write Enable Input", 6 A18 (in) "Address Input", 7 A15 (in) "Address Input", 8 VDD (power) "Power", 9 A17 (in) "Address Input", 10 A16 (in) "Address Input", 11 A14 (in) "Address Input", 12 A12 (in) "Address Input", 13 A7 (in) "Address Input", 14 A6 (in) "Address Input", 15 A5 (in) "Address Input", 16 A4 (in) "Address Input", 17 A3 (in) "Address Input", 18 A2 (in) "Address Input", 19 A1 (in) "Address Input", 20 A0 (in) "Address Input", 21 I/O0 (io) "Input/Output", 22 I/O1 (io) "Input/Output", 23 I/O2 (io) "Input/Output", 24 GND (power) "Ground", 25 I/O3 (io) "Input/Output", 26 I/O4 (io) "Input/Output", 27 I/O5 (io) "Input/Output", 28 I/O6 (io) "Input/Output", 29 I/O7 (io) "Input/Output", 30 ~{CE} (in) "Chip Enable 1 Input", 31 A10 (in) "Address Input", 32 ~{OE} (in) "Output Enable Input"

## IS62C5128BL-45TI
designator U?
4 M High Speed CMOS SRAM, 512 K x 8, -40 to 85 degC, 32-Pin SOP (TSOP-2-32); Manufacturer: Integrated Silicon Solution Inc (ISSI); PartNumber: IS62C5128BL-45TI; Density: 4M; Organization: 512K x 8; Packing: Tray / Tube; Speed (ns): 45
footprint ISSI-TSOP-2-32_N (SOP, 32-Leads, Body 21.1x10.3mm, Pitch 1.27mm, IPC Medium Density)
pins: 1 A17 (in) "Address Input", 2 A16 (in) "Address Input", 3 A14 (in) "Address Input", 4 A12 (in) "Address Input", 5 A7 (in) "Address Input", 6 A6 (in) "Address Input", 7 A5 (in) "Address Input", 8 A4 (in) "Address Input", 9 A3 (in) "Address Input", 10 A2 (in) "Address Input", 11 A1 (in) "Address Input", 12 A0 (in) "Address Input", 13 I/O0 (io) "Input/Output", 14 I/O1 (io) "Input/Output", 15 I/O2 (io) "Input/Output", 16 GND (power) "Ground", 17 I/O3 (io) "Input/Output", 18 I/O4 (io) "Input/Output", 19 I/O5 (io) "Input/Output", 20 I/O6 (io) "Input/Output", 21 I/O7 (io) "Input/Output", 22 ~{CE} (in) "Chip Enable 1 Input", 23 A10 (in) "Address Input", 24 ~{OE} (in) "Output Enable Input", 25 A11 (in) "Address Input", 26 A9 (in) "Address Input", 27 A8 (in) "Address Input", 28 A13 (in) "Address Input", 29 ~{WE} (in) "Write Enable Input", 30 A18 (in) "Address Input", 31 A15 (in) "Address Input", 32 VDD (power) "Power"

## IS62C5128BL-45TI-TR
designator U?
4 M High Speed CMOS SRAM, 512 K x 8, -40 to 85 degC, 32-Pin SOP (TSOP-2-32); Manufacturer: Integrated Silicon Solution Inc (ISSI); PartNumber: IS62C5128BL-45TI-TR; Density: 4M; Organization: 512K x 8; Packing: Tape & Reel; Speed (ns): 45
footprint ISSI-TSOP-2-32_N (SOP, 32-Leads, Body 21.1x10.3mm, Pitch 1.27mm, IPC Medium Density)
pins: 1 A17 (in) "Address Input", 2 A16 (in) "Address Input", 3 A14 (in) "Address Input", 4 A12 (in) "Address Input", 5 A7 (in) "Address Input", 6 A6 (in) "Address Input", 7 A5 (in) "Address Input", 8 A4 (in) "Address Input", 9 A3 (in) "Address Input", 10 A2 (in) "Address Input", 11 A1 (in) "Address Input", 12 A0 (in) "Address Input", 13 I/O0 (io) "Input/Output", 14 I/O1 (io) "Input/Output", 15 I/O2 (io) "Input/Output", 16 GND (power) "Ground", 17 I/O3 (io) "Input/Output", 18 I/O4 (io) "Input/Output", 19 I/O5 (io) "Input/Output", 20 I/O6 (io) "Input/Output", 21 I/O7 (io) "Input/Output", 22 ~{CE} (in) "Chip Enable 1 Input", 23 A10 (in) "Address Input", 24 ~{OE} (in) "Output Enable Input", 25 A11 (in) "Address Input", 26 A9 (in) "Address Input", 27 A8 (in) "Address Input", 28 A13 (in) "Address Input", 29 ~{WE} (in) "Write Enable Input", 30 A18 (in) "Address Input", 31 A15 (in) "Address Input", 32 VDD (power) "Power"

## IS62C5128BL-45TLI
designator U?
4 M High Speed CMOS SRAM, 512 K x 8, -40 to 85 degC, 32-Pin SOP (TSOP-2-32), Pb-Free; Manufacturer: Integrated Silicon Solution Inc (ISSI); PartNumber: IS62C5128BL-45TLI; Density: 4M; Organization: 512K x 8; Packing: Tray / Tube; Speed (ns): 45
footprint ISSI-TSOP-2-32_N (SOP, 32-Leads, Body 21.1x10.3mm, Pitch 1.27mm, IPC Medium Density)
pins: 1 A17 (in) "Address Input", 2 A16 (in) "Address Input", 3 A14 (in) "Address Input", 4 A12 (in) "Address Input", 5 A7 (in) "Address Input", 6 A6 (in) "Address Input", 7 A5 (in) "Address Input", 8 A4 (in) "Address Input", 9 A3 (in) "Address Input", 10 A2 (in) "Address Input", 11 A1 (in) "Address Input", 12 A0 (in) "Address Input", 13 I/O0 (io) "Input/Output", 14 I/O1 (io) "Input/Output", 15 I/O2 (io) "Input/Output", 16 GND (power) "Ground", 17 I/O3 (io) "Input/Output", 18 I/O4 (io) "Input/Output", 19 I/O5 (io) "Input/Output", 20 I/O6 (io) "Input/Output", 21 I/O7 (io) "Input/Output", 22 ~{CE} (in) "Chip Enable 1 Input", 23 A10 (in) "Address Input", 24 ~{OE} (in) "Output Enable Input", 25 A11 (in) "Address Input", 26 A9 (in) "Address Input", 27 A8 (in) "Address Input", 28 A13 (in) "Address Input", 29 ~{WE} (in) "Write Enable Input", 30 A18 (in) "Address Input", 31 A15 (in) "Address Input", 32 VDD (power) "Power"

## IS62C5128BL-45TLI-TR
designator U?
4 M High Speed CMOS SRAM, 512 K x 8, -40 to 85 degC, 32-Pin SOP (TSOP-2-32), Pb-Free; Manufacturer: Integrated Silicon Solution Inc (ISSI); PartNumber: IS62C5128BL-45TLI-TR; Density: 4M; Organization: 512K x 8; Packing: Tape & Reel; Speed (ns): 45
footprint ISSI-TSOP-2-32_N (SOP, 32-Leads, Body 21.1x10.3mm, Pitch 1.27mm, IPC Medium Density)
pins: 1 A17 (in) "Address Input", 2 A16 (in) "Address Input", 3 A14 (in) "Address Input", 4 A12 (in) "Address Input", 5 A7 (in) "Address Input", 6 A6 (in) "Address Input", 7 A5 (in) "Address Input", 8 A4 (in) "Address Input", 9 A3 (in) "Address Input", 10 A2 (in) "Address Input", 11 A1 (in) "Address Input", 12 A0 (in) "Address Input", 13 I/O0 (io) "Input/Output", 14 I/O1 (io) "Input/Output", 15 I/O2 (io) "Input/Output", 16 GND (power) "Ground", 17 I/O3 (io) "Input/Output", 18 I/O4 (io) "Input/Output", 19 I/O5 (io) "Input/Output", 20 I/O6 (io) "Input/Output", 21 I/O7 (io) "Input/Output", 22 ~{CE} (in) "Chip Enable 1 Input", 23 A10 (in) "Address Input", 24 ~{OE} (in) "Output Enable Input", 25 A11 (in) "Address Input", 26 A9 (in) "Address Input", 27 A8 (in) "Address Input", 28 A13 (in) "Address Input", 29 ~{WE} (in) "Write Enable Input", 30 A18 (in) "Address Input", 31 A15 (in) "Address Input", 32 VDD (power) "Power"

## IS62C10248AL-55MLI
designator U?
8 M Low Voltage, Ultra Low Power CMOS SRAM, 1 M x 8, -40 to 85 degC, 48-Pin BGA (TF-BGA-48), Pb-Free; Manufacturer: Integrated Silicon Solution Inc (ISSI); PartNumber: IS62C10248AL-55MLI; Density: 8M; Organization: 1M x 8; Packing: Tray / Tube; Speed (ns): 55
footprint ISSI-TF-BGA-48-9000x11000DE (BGA, 48-Balls, Body 11x9mm, Pitch 0.75mm)
part A pins: A2 ~{OE} (in) "Output Enable Input", A3 A0 (in) "Address Inputs", A4 A1 (in) "Address Inputs", A5 A2 (in) "Address Inputs", A6 CS2 (in) "Chip Enable 2 Input", B3 A3 (in) "Address Inputs", B4 A4 (in) "Address Inputs", B5 ~{CS1} (in) "Chip Enable 1 Input", C1 I/O0 (io) "Input/Output", C3 A5 (in) "Address Inputs", C4 A6 (in) "Address Inputs", C6 I/O4 (io) "Input/Output", D1 GND (power) "Ground", D2 I/O1 (io) "Input/Output", D3 A17 (in) "Address Inputs", D4 A7 (in) "Address Inputs", D5 I/O5 (io) "Input/Output", D6 VDD (power) "Power", E1 VDD (power) "Power", E2 I/O2 (io) "Input/Output", E4 A16 (in) "Address Inputs", E5 I/O6 (io) "Input/Output", E6 VSS (power) "Power", F1 I/O3 (io) "Input/Output", F3 A14 (in) "Address Inputs", F4 A15 (in) "Address Inputs", F6 I/O7 (io) "Input/Output", G3 A12 (in) "Address Inputs", G4 A13 (in) "Address Inputs", G5 ~{WE} (in) "Write Enable Input", H1 A18 (in) "Address Inputs", H2 A8 (in) "Address Inputs", H3 A9 (in) "Address Inputs", H4 A10 (in) "Address Inputs", H5 A11 (in) "Address Inputs", H6 A19 (in) "Address Inputs"
part B pins: A1 NC "No Connection", B1 NC "No Connection", B2 NC "No Connection", B6 NC "No Connection", C2 NC "No Connection", C5 NC "No Connection", E3 NC "No Connection", F2 NC "No Connection", F5 NC "No Connection", G1 NC "No Connection", G2 NC "No Connection", G6 NC "No Connection"

## IS62C10248AL-55MLI-TR
designator U?
8 M Low Voltage, Ultra Low Power CMOS SRAM, 1 M x 8, -40 to 85 degC, 48-Pin BGA (TF-BGA-48), Pb-Free; Manufacturer: Integrated Silicon Solution Inc (ISSI); PartNumber: IS62C10248AL-55MLI-TR; Density: 8M; Organization: 1M x 8; Packing: Tape & Reel; Speed (ns): 55
footprint ISSI-TF-BGA-48-9000x11000DE (BGA, 48-Balls, Body 11x9mm, Pitch 0.75mm)
part A pins: A2 ~{OE} (in) "Output Enable Input", A3 A0 (in) "Address Inputs", A4 A1 (in) "Address Inputs", A5 A2 (in) "Address Inputs", A6 CS2 (in) "Chip Enable 2 Input", B3 A3 (in) "Address Inputs", B4 A4 (in) "Address Inputs", B5 ~{CS1} (in) "Chip Enable 1 Input", C1 I/O0 (io) "Input/Output", C3 A5 (in) "Address Inputs", C4 A6 (in) "Address Inputs", C6 I/O4 (io) "Input/Output", D1 GND (power) "Ground", D2 I/O1 (io) "Input/Output", D3 A17 (in) "Address Inputs", D4 A7 (in) "Address Inputs", D5 I/O5 (io) "Input/Output", D6 VDD (power) "Power", E1 VDD (power) "Power", E2 I/O2 (io) "Input/Output", E4 A16 (in) "Address Inputs", E5 I/O6 (io) "Input/Output", E6 VSS (power) "Power", F1 I/O3 (io) "Input/Output", F3 A14 (in) "Address Inputs", F4 A15 (in) "Address Inputs", F6 I/O7 (io) "Input/Output", G3 A12 (in) "Address Inputs", G4 A13 (in) "Address Inputs", G5 ~{WE} (in) "Write Enable Input", H1 A18 (in) "Address Inputs", H2 A8 (in) "Address Inputs", H3 A9 (in) "Address Inputs", H4 A10 (in) "Address Inputs", H5 A11 (in) "Address Inputs", H6 A19 (in) "Address Inputs"
part B pins: A1 NC "No Connection", B1 NC "No Connection", B2 NC "No Connection", B6 NC "No Connection", C2 NC "No Connection", C5 NC "No Connection", E3 NC "No Connection", F2 NC "No Connection", F5 NC "No Connection", G1 NC "No Connection", G2 NC "No Connection", G6 NC "No Connection"

## IS62C10248AL-55TLI
designator U?
8 M Low Voltage, Ultra Low Power CMOS SRAM, 1 M x 8, -40 to 85 degC, 44-Pin SOP (TSOP-2-44), Pb-Free; Manufacturer: Integrated Silicon Solution Inc (ISSI); PartNumber: IS62C10248AL-55TLI; Density: 8M; Organization: 1M x 8; Packing: Tray / Tube; Speed (ns): 55
footprint ISSI-TSOP-2-44_N (SOP, 44-Leads, Body 18.5x10.3mm, Pitch 0.8mm, IPC Medium Density)
part A pins: 1 A4 (in) "Address Input", 2 A3 (in) "Address Input", 3 A2 (in) "Address Input", 4 A1 (in) "Address Input", 5 A0 (in) "Address Input", 6 ~{CS1} (in) "Chip Enable 1 Input", 9 I/O0 (io) "Input/Output", 10 I/O1 (io) "Input/Output", 11 VDD (power) "Power", 12 GND (power) "Ground", 13 I/O2 (io) "Input/Output", 14 I/O3 (io) "Input/Output", 17 ~{WE} (in) "Write Enable Input", 18 A19 (in) "Address Input", 19 A18 (in) "Address Input", 20 A17 (in) "Address Input", 21 A16 (in) "Address Input", 22 A15 (in) "Address Input", 23 A14 (in) "Address Input", 24 A13 (in) "Address Input", 25 A12 (in) "Address Input", 26 A11 (in) "Address Input", 27 A10 (in) "Address Input", 28 A9 (in) "Address Input", 31 I/O4 (io) "Input/Output", 32 I/O5 (io) "Input/Output", 33 VDD (power) "Power", 34 GND (power) "Ground", 35 I/O6 (io) "Input/Output", 36 I/O7 (io) "Input/Output", 39 A8 (in) "Address Input", 40 CS2 (in) "Chip Enable 2 Input", 41 ~{OE} (in) "Output Enable Input", 42 A7 (in) "Address Input", 43 A6 (in) "Address Input", 44 A5 (in) "Address Input"
part B pins: 7 NC "No Connection", 8 NC "No Connection", 15 NC "No Connection", 16 NC "No Connection", 29 NC "No Connection", 30 NC "No Connection", 37 NC "No Connection", 38 NC "No Connection"

## IS62C10248AL-55TLI-TR
designator U?
8 M Low Voltage, Ultra Low Power CMOS SRAM, 1 M x 8, -40 to 85 degC, 44-Pin SOP (TSOP-2-44), Pb-Free; Manufacturer: Integrated Silicon Solution Inc (ISSI); PartNumber: IS62C10248AL-55TLI-TR; Density: 8M; Organization: 1M x 8; Packing: Tape & Reel; Speed (ns): 55
footprint ISSI-TSOP-2-44_N (SOP, 44-Leads, Body 18.5x10.3mm, Pitch 0.8mm, IPC Medium Density)
part A pins: 1 A4 (in) "Address Input", 2 A3 (in) "Address Input", 3 A2 (in) "Address Input", 4 A1 (in) "Address Input", 5 A0 (in) "Address Input", 6 ~{CS1} (in) "Chip Enable 1 Input", 9 I/O0 (io) "Input/Output", 10 I/O1 (io) "Input/Output", 11 VDD (power) "Power", 12 GND (power) "Ground", 13 I/O2 (io) "Input/Output", 14 I/O3 (io) "Input/Output", 17 ~{WE} (in) "Write Enable Input", 18 A19 (in) "Address Input", 19 A18 (in) "Address Input", 20 A17 (in) "Address Input", 21 A16 (in) "Address Input", 22 A15 (in) "Address Input", 23 A14 (in) "Address Input", 24 A13 (in) "Address Input", 25 A12 (in) "Address Input", 26 A11 (in) "Address Input", 27 A10 (in) "Address Input", 28 A9 (in) "Address Input", 31 I/O4 (io) "Input/Output", 32 I/O5 (io) "Input/Output", 33 VDD (power) "Power", 34 GND (power) "Ground", 35 I/O6 (io) "Input/Output", 36 I/O7 (io) "Input/Output", 39 A8 (in) "Address Input", 40 CS2 (in) "Chip Enable 2 Input", 41 ~{OE} (in) "Output Enable Input", 42 A7 (in) "Address Input", 43 A6 (in) "Address Input", 44 A5 (in) "Address Input"
part B pins: 7 NC "No Connection", 8 NC "No Connection", 15 NC "No Connection", 16 NC "No Connection", 29 NC "No Connection", 30 NC "No Connection", 37 NC "No Connection", 38 NC "No Connection"

## IS62C25616BL-45TI
designator U?
4 M High Speed CMOS SRAM, 256 K x 16, -40 to 85 degC, 44-Pin SOP (TSOP-2-44); Manufacturer: Integrated Silicon Solution Inc (ISSI); PartNumber: IS62C25616BL-45TI; Density: 4M; Packing: Tray / Tube; Speed (ns): 45
footprint ISSI-TSOP-2-44_N (SOP, 44-Leads, Body 18.5x10.3mm, Pitch 0.8mm, IPC Medium Density)
pins: 1 A4 (in) "Address Input", 2 A3 (in) "Address Input", 3 A2 (in) "Address Input", 4 A1 (in) "Address Input", 5 A0 (in) "Address Input", 6 ~{CE} (in) "Chip Enable Input", 7 I/O0 (io) "Data Input/Output", 8 I/O1 (io) "Data Input/Output", 9 I/O2 (io) "Data Input/Output", 10 I/O3 (io) "Data Input/Output", 11 VDD (power) "Power", 12 GND (power) "Ground", 13 I/O4 (io) "Data Input/Output", 14 I/O5 (io) "Data Input/Output", 15 I/O6 (io) "Data Input/Output", 16 I/O7 (io) "Data Input/Output", 17 ~{WE} (in) "Write Enable Input", 18 A16 (in) "Address Input", 19 A15 (in) "Address Input", 20 A14 (in) "Address Input", 21 A13 (in) "Address Input", 22 A12 (in) "Address Input", 23 A17 (in) "Address Input", 24 A11 (in) "Address Input", 25 A10 (in) "Address Input", 26 A9 (in) "Address Input", 27 A8 (in) "Address Input", 28 NC "No Connection", 29 I/O8 (io) "Data Input/Output", 30 I/O9 (io) "Data Input/Output", 31 I/O10 (io) "Data Input/Output", 32 I/O11 (io) "Data Input/Output", 33 VDD (power) "Power", 34 GND (power) "Ground", 35 I/O12 (io) "Data Input/Output", 36 I/O13 (io) "Data Input/Output", 37 I/O14 (io) "Data Inputs/Outputs", 38 I/O15 (io) "Data Input/Output", 39 ~{LB} (in) "Lower-byte Control (I/O0-I/O7)", 40 ~{UB} (in) "Upper-byte Control (I/O8-I/O15)", 41 ~{OE} (in) "Output Enable Input", 42 A7 (in) "Address Input", 43 A6 (in) "Address Input", 44 A5 (in) "Address Input"

## IS62C25616BL-45TI-TR
designator U?
4 M High Speed CMOS SRAM, 256 K x 16, -40 to 85 degC, 44-Pin SOP (TSOP-2-44); Manufacturer: Integrated Silicon Solution Inc (ISSI); PartNumber: IS62C25616BL-45TI-TR; Density: 4M; Packing: Tape & Reel; Speed (ns): 45
footprint ISSI-TSOP-2-44_N (SOP, 44-Leads, Body 18.5x10.3mm, Pitch 0.8mm, IPC Medium Density)
pins: 1 A4 (in) "Address Input", 2 A3 (in) "Address Input", 3 A2 (in) "Address Input", 4 A1 (in) "Address Input", 5 A0 (in) "Address Input", 6 ~{CE} (in) "Chip Enable Input", 7 I/O0 (io) "Data Input/Output", 8 I/O1 (io) "Data Input/Output", 9 I/O2 (io) "Data Input/Output", 10 I/O3 (io) "Data Input/Output", 11 VDD (power) "Power", 12 GND (power) "Ground", 13 I/O4 (io) "Data Input/Output", 14 I/O5 (io) "Data Input/Output", 15 I/O6 (io) "Data Input/Output", 16 I/O7 (io) "Data Input/Output", 17 ~{WE} (in) "Write Enable Input", 18 A16 (in) "Address Input", 19 A15 (in) "Address Input", 20 A14 (in) "Address Input", 21 A13 (in) "Address Input", 22 A12 (in) "Address Input", 23 A17 (in) "Address Input", 24 A11 (in) "Address Input", 25 A10 (in) "Address Input", 26 A9 (in) "Address Input", 27 A8 (in) "Address Input", 28 NC "No Connection", 29 I/O8 (io) "Data Input/Output", 30 I/O9 (io) "Data Input/Output", 31 I/O10 (io) "Data Input/Output", 32 I/O11 (io) "Data Input/Output", 33 VDD (power) "Power", 34 GND (power) "Ground", 35 I/O12 (io) "Data Input/Output", 36 I/O13 (io) "Data Input/Output", 37 I/O14 (io) "Data Inputs/Outputs", 38 I/O15 (io) "Data Input/Output", 39 ~{LB} (in) "Lower-byte Control (I/O0-I/O7)", 40 ~{UB} (in) "Upper-byte Control (I/O8-I/O15)", 41 ~{OE} (in) "Output Enable Input", 42 A7 (in) "Address Input", 43 A6 (in) "Address Input", 44 A5 (in) "Address Input"

## IS62C25616BL-45TLI
designator U?
4 M High Speed CMOS SRAM, 256 K x 16, -40 to 85 degC, 44-Pin SOP (TSOP-2-44), Pb-Free; Manufacturer: Integrated Silicon Solution Inc (ISSI); PartNumber: IS62C25616BL-45TLI; Density: 4M; Packing: Tray / Tube; Speed (ns): 45
footprint ISSI-TSOP-2-44_N (SOP, 44-Leads, Body 18.5x10.3mm, Pitch 0.8mm, IPC Medium Density)
pins: 1 A4 (in) "Address Input", 2 A3 (in) "Address Input", 3 A2 (in) "Address Input", 4 A1 (in) "Address Input", 5 A0 (in) "Address Input", 6 ~{CE} (in) "Chip Enable Input", 7 I/O0 (io) "Data Input/Output", 8 I/O1 (io) "Data Input/Output", 9 I/O2 (io) "Data Input/Output", 10 I/O3 (io) "Data Input/Output", 11 VDD (power) "Power", 12 GND (power) "Ground", 13 I/O4 (io) "Data Input/Output", 14 I/O5 (io) "Data Input/Output", 15 I/O6 (io) "Data Input/Output", 16 I/O7 (io) "Data Input/Output", 17 ~{WE} (in) "Write Enable Input", 18 A16 (in) "Address Input", 19 A15 (in) "Address Input", 20 A14 (in) "Address Input", 21 A13 (in) "Address Input", 22 A12 (in) "Address Input", 23 A17 (in) "Address Input", 24 A11 (in) "Address Input", 25 A10 (in) "Address Input", 26 A9 (in) "Address Input", 27 A8 (in) "Address Input", 28 NC "No Connection", 29 I/O8 (io) "Data Input/Output", 30 I/O9 (io) "Data Input/Output", 31 I/O10 (io) "Data Input/Output", 32 I/O11 (io) "Data Input/Output", 33 VDD (power) "Power", 34 GND (power) "Ground", 35 I/O12 (io) "Data Input/Output", 36 I/O13 (io) "Data Input/Output", 37 I/O14 (io) "Data Inputs/Outputs", 38 I/O15 (io) "Data Input/Output", 39 ~{LB} (in) "Lower-byte Control (I/O0-I/O7)", 40 ~{UB} (in) "Upper-byte Control (I/O8-I/O15)", 41 ~{OE} (in) "Output Enable Input", 42 A7 (in) "Address Input", 43 A6 (in) "Address Input", 44 A5 (in) "Address Input"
